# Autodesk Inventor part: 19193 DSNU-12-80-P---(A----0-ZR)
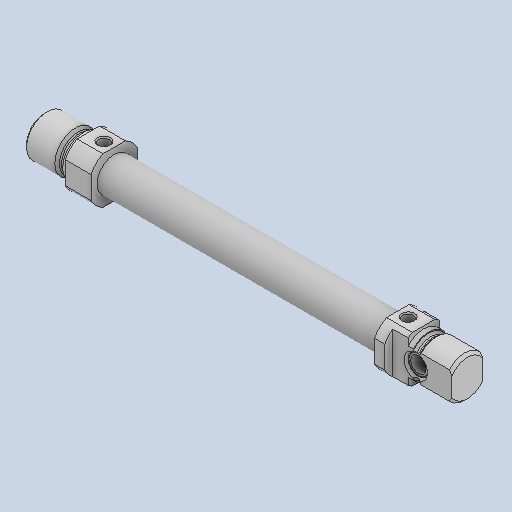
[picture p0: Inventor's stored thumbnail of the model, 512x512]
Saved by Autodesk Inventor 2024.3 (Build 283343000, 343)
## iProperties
Created: 2024-12
Part Number: 19193 DSNU-12-80-P---(A----0-ZR)
Material: Generic
Description: 19193 DSNU-12-80-P---(A----0-ZR)
Document SubType Name: Modeling
Designer: ruhr
Density: 1 g/cm^3
Appearance: Default
Author: ruhr
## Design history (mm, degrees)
feature "19193 DSNU-12-80-P---(A----0-ZR)"
body "Solid1"
